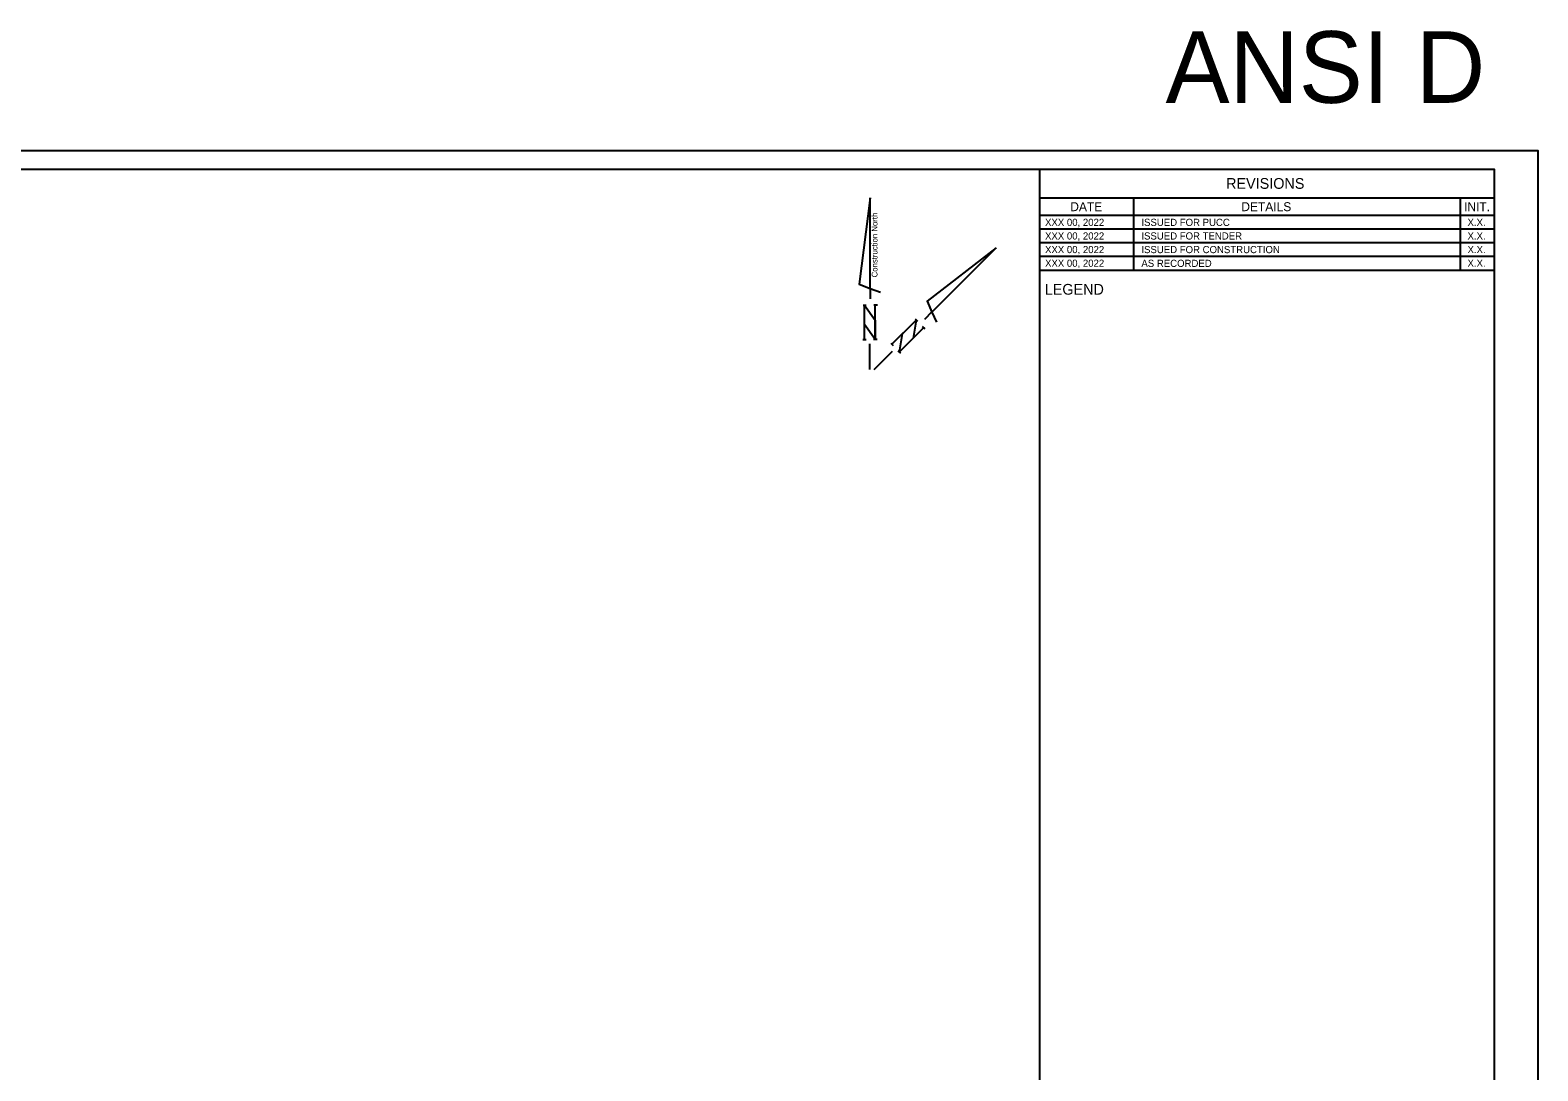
# Model space of a CAD drawing. Extents: x 612883 to 613093, y 4825734 to 4825879.
# Drawn here: x 612988 to 613093.1, y 4825806.3 to 4825878.9 of the extents above; entities that cross this region are included whole.
import ezdxf

# ---------------------------------------------------------------- set-up
doc = ezdxf.new("R2010")
doc.units = 0
for name, color, linetype in [('G-ANNO-LEGN', 7, 'Continuous'), ('G-ANNO-NPLT', 7, 'Continuous'), ('G-ANNO-SYMB', 7, 'Continuous'), ('G-ANNO-TTLB-TEXT', 7, 'Continuous'), ('G-TTLB-OTLN', 7, 'Continuous'), ('G-TTLB-OTLN-PB', 7, 'Continuous')]:
    doc.layers.add(name, color=color, linetype=linetype)

msp = doc.modelspace()

# ---------------------------------------------------------------- linework, layer by layer
at = {"layer": 'G-ANNO-SYMB'}
for p, q in [((613046.56, 4825860.89), (613046.56, 4825860.14)), ((613046.57, 4825860.88), (613047.28, 4825860.61)), ((613046.07, 4825859.71), (613046.3, 4825859.71)), ((613046.18, 4825857.31), (613046.18, 4825859.71)), ((613047.07, 4825859.71), (613046.82, 4825859.71)), ((613046.93, 4825857.31), (613046.93, 4825859.71)), ((613050.88, 4825859.24), (613050.35, 4825858.71)), ((613050.88, 4825859.23), (613051.2, 4825858.53)), ((613048.08, 4825856.98), (613049.78, 4825858.67)), ((613048.61, 4825856.45), (613050.31, 4825858.14)), ((613049.7, 4825858.75), (613049.87, 4825858.59)), ((613050.41, 4825858.05), (613050.23, 4825858.22)), ((613046.06, 4825857.31), (613046.3, 4825857.31)), ((613046.55, 4825855.21), (613046.55, 4825857)), ((613047.06, 4825857.31), (613046.81, 4825857.31)), ((613048, 4825857.06), (613048.17, 4825856.89)), ((613046.86, 4825855.23), (613048.13, 4825856.5)), ((613048.71, 4825856.35), (613048.53, 4825856.53))]:
    msp.add_line(p, q, dxfattribs=at)
for points in [[(613046.57, 4825867.21), (613045.8, 4825861.18), (613046.57, 4825860.88)], [(613055.36, 4825863.7), (613050.55, 4825859.98), (613050.88, 4825859.23)], [(613046.93, 4825857.32), (613046.18, 4825858.36), (613046.18, 4825859.71), (613046.93, 4825858.66)], [(613048.62, 4825856.45), (613048.83, 4825857.72), (613049.79, 4825858.67), (613049.57, 4825857.4)]]:
    msp.add_lwpolyline(points, close=True, dxfattribs=at)
at = {"layer": 'G-TTLB-OTLN'}
for p, q in [((613058.4, 4825734.93), (613058.4, 4825869.21)), ((613058.4, 4825867.21), (613090.1, 4825867.21)), ((613064.93, 4825867.21), (613064.93, 4825862.16)), ((613087.73, 4825867.21), (613087.73, 4825862.16)), ((613090.1, 4825865.96), (613058.4, 4825865.96)), ((613090.1, 4825865.01), (613058.4, 4825865.01)), ((613090.1, 4825864.06), (613058.4, 4825864.06)), ((613090.1, 4825863.11), (613058.4, 4825863.11)), ((613058.4, 4825862.16), (613090.1, 4825862.16))]:
    msp.add_line(p, q, dxfattribs=at)
msp.add_lwpolyline([(612893.05, 4825869.21), (613090.1, 4825869.21), (613090.1, 4825734.93), (612893.05, 4825734.93)], close=True, dxfattribs=at)
at = {"layer": 'G-TTLB-OTLN-PB'}
for p, q in [((613090.5, 4825870.51), (613093.15, 4825870.51)), ((613093.15, 4825870.51), (613093.15, 4825867.51))]:
    msp.add_line(p, q, dxfattribs=at)
msp.add_lwpolyline([(612882.8, 4825870.51), (613093.15, 4825870.51), (613093.15, 4825733.63), (612882.8, 4825733.63)], close=True, dxfattribs=at)

# ---------------------------------------------------------------- texts
at = {"layer": 'G-ANNO-LEGN'}
msp.add_text('LEGEND', height=0.75, rotation=0.0057, dxfattribs=at).set_placement((613058.75, 4825860.44))
at = {"layer": 'G-ANNO-NPLT'}
msp.add_text('ANSI D', height=5, dxfattribs=at).set_placement((613067.18, 4825873.83))
at = {"layer": 'G-ANNO-SYMB'}
msp.add_text('Construction North', height=0.405, rotation=89.9998, dxfattribs=at).set_placement((613047.08, 4825861.65))
at = {"layer": 'G-ANNO-TTLB-TEXT'}
for s, height, p in [('REVISIONS', 0.75, (613071.4, 4825867.83)), ('DATE', 0.625, (613060.53, 4825866.27)), ('DETAILS', 0.625, (613072.46, 4825866.27)), ('INIT.', 0.625, (613088, 4825866.27)), ('XXX 00, 2022', 0.5, (613058.77, 4825863.34)), ('XXX 00, 2022', 0.5, (613058.77, 4825862.39))]:
    msp.add_text(s, height=height, dxfattribs=at).set_placement(p)
for s, p in [('XXX 00, 2022', (613058.77, 4825865.24)), ('ISSUED FOR PUCC', (613065.49, 4825865.24)), ('X.X.', (613088.24, 4825865.24)), ('XXX 00, 2022', (613058.77, 4825864.29)), ('ISSUED FOR TENDER', (613065.49, 4825864.29)), ('X.X.', (613088.24, 4825864.29)), ('ISSUED FOR CONSTRUCTION', (613065.49, 4825863.34)), ('X.X.', (613088.24, 4825863.34)), ('AS RECORDED', (613065.49, 4825862.38)), ('X.X.', (613088.24, 4825862.39))]:
    msp.add_text(s, height=0.5, rotation=360, dxfattribs=at).set_placement(p)

doc.saveas('drawing.dxf')
